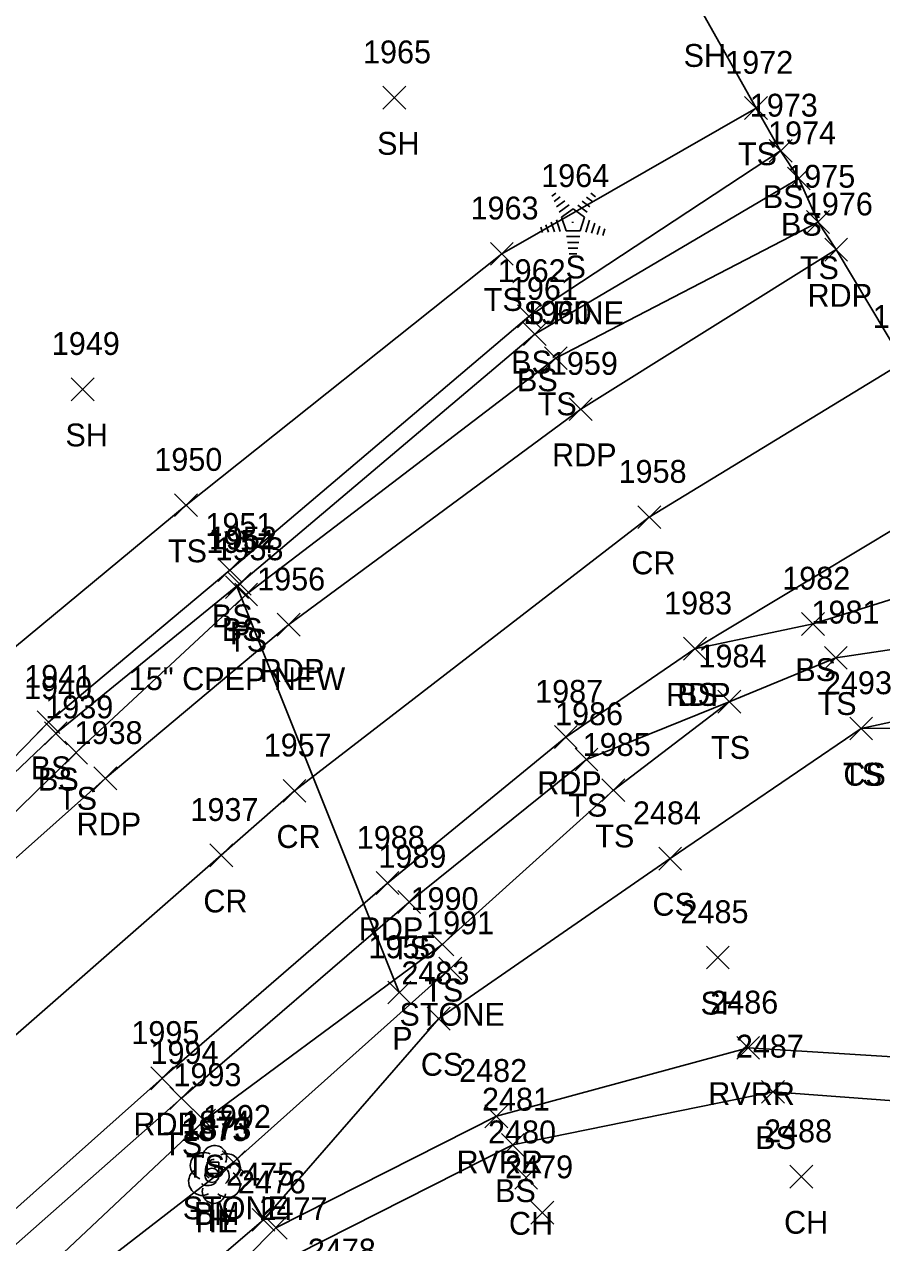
# Model space of a CAD drawing. Extents: x 1459992 to 1461532, y 647785 to 648535.
# Drawn here: x 1461347.9 to 1461422.9, y 648356.5 to 648463.1 of the extents above; entities that cross this region are included whole.
import ezdxf

# ---------------------------------------------------------------- set-up
doc = ezdxf.new("R2010")
doc.units = 0
for name, color, linetype in [('C_A', 7, 'Continuous'), ('C_I', 7, 'Continuous'), ('CBP', 7, 'Continuous'), ('CPBM', 7, 'Continuous'), ('D_A', 7, 'Continuous'), ('D_C', 7, 'Continuous'), ('D_I', 7, 'Continuous'), ('D_TIC', 7, 'Continuous'), ('DCP', 7, 'Continuous'), ('L_A', 7, 'Continuous'), ('L_C', 7, 'Continuous'), ('L_I', 7, 'Continuous'), ('L_TIC', 7, 'Continuous'), ('LASF', 7, 'Continuous'), ('LAWE', 7, 'Continuous'), ('LELB', 7, 'Continuous'), ('LSOGP', 7, 'Continuous'), ('LTC', 7, 'Continuous'), ('LTD', 7, 'Continuous'), ('P_A', 7, 'Continuous'), ('P_I', 7, 'Continuous'), ('P_TIC', 7, 'Continuous'), ('PET', 7, 'Continuous'), ('PRC', 7, 'Continuous')]:
    doc.layers.add(name, color=color, linetype=linetype)

msp = doc.modelspace()

# ---------------------------------------------------------------- linework, layer by layer
at = {"layer": 'CBP'}
for radius in [0.625, 0.0833]:
    msp.add_circle((1461364.35, 648362.4), radius, dxfattribs=at)
at = {"layer": 'CPBM'}
for p, q in [((1461363.94, 648362.56), (1461363.94, 648363.56)), ((1461363.94, 648363.56), (1461364.94, 648363.56)), ((1461364.94, 648363.56), (1461364.94, 648362.56)), ((1461364.94, 648362.56), (1461363.94, 648362.56)), ((1461364.44, 648363.06), (1461364.44, 648363.06)), ((1461364.44, 648363.06), (1461364.44, 648363.06))]:
    msp.add_line(p, q, dxfattribs=at)
at = {"layer": 'D_TIC'}
for points in [[(1461365.55, 648412.85), (1461367.55, 648414.85)], [(1461367.55, 648412.85), (1461365.55, 648414.85)], [(1461379.74, 648377.39), (1461381.74, 648379.39)], [(1461381.74, 648377.39), (1461379.74, 648379.39)]]:
    msp.add_lwpolyline(points, dxfattribs=at)
at = {"layer": 'DCP'}
msp.add_lwpolyline([(1461366.55, 648413.85), (1461380.74, 648378.39)], dxfattribs=at)
at = {"layer": 'L_TIC'}
for points in [[(1461379.31, 648455.68), (1461381.31, 648457.68)], [(1461381.31, 648455.68), (1461379.31, 648457.68)], [(1461410.96, 648454.77), (1461412.96, 648456.77)], [(1461412.96, 648454.77), (1461410.96, 648456.77)], [(1461413.11, 648451.02), (1461415.11, 648453.02)], [(1461415.11, 648451.02), (1461413.11, 648453.02)], [(1461414.7, 648448.6), (1461416.7, 648450.6)], [(1461416.7, 648448.6), (1461414.7, 648450.6)], [(1461416.38, 648444.8), (1461418.38, 648446.8)], [(1461418.38, 648444.8), (1461416.38, 648446.8)], [(1461388.72, 648442.02), (1461390.72, 648444.02)], [(1461390.72, 648442.02), (1461388.72, 648444.02)], [(1461391.09, 648436.54), (1461393.09, 648438.54)], [(1461393.09, 648436.54), (1461391.09, 648438.54)], [(1461391.6, 648434.99), (1461393.6, 648436.99)], [(1461393.6, 648434.99), (1461391.6, 648436.99)], [(1461393.44, 648432.89), (1461395.44, 648434.89)], [(1461395.44, 648432.89), (1461393.44, 648434.89)], [(1461352.04, 648430.17), (1461354.04, 648432.17)], [(1461354.04, 648430.17), (1461352.04, 648432.17)], [(1461361.09, 648420.03), (1461363.09, 648422.03)], [(1461363.09, 648420.03), (1461361.09, 648422.03)], [(1461364.91, 648414.34), (1461366.91, 648416.34)], [(1461366.91, 648414.34), (1461364.91, 648416.34)], [(1461365.77, 648413.15), (1461367.77, 648415.15)], [(1461367.77, 648413.15), (1461365.77, 648415.15)], [(1461366.35, 648412.21), (1461368.35, 648414.21)], [(1461368.35, 648412.21), (1461366.35, 648414.21)], [(1461415.95, 648409.64), (1461417.95, 648411.64)], [(1461417.95, 648409.64), (1461415.95, 648411.64)], [(1461405.61, 648407.47), (1461407.61, 648409.47)], [(1461407.61, 648407.47), (1461405.61, 648409.47)], [(1461417.94, 648406.67), (1461419.94, 648408.67)], [(1461419.94, 648406.67), (1461417.94, 648408.67)], [(1461408.62, 648402.83), (1461410.62, 648404.83)], [(1461410.62, 648402.83), (1461408.62, 648404.83)], [(1461408.62, 648402.83), (1461410.62, 648404.83)], [(1461410.62, 648402.83), (1461408.62, 648404.83)], [(1461349.05, 648401.05), (1461351.05, 648403.05)], [(1461351.05, 648401.05), (1461349.05, 648403.05)], [(1461349.69, 648400.06), (1461351.69, 648402.06)], [(1461351.69, 648400.06), (1461349.69, 648402.06)], [(1461420.16, 648400.49), (1461422.16, 648402.49)], [(1461422.16, 648400.49), (1461420.16, 648402.49)], [(1461420.16, 648400.49), (1461422.16, 648402.49)], [(1461422.16, 648400.49), (1461420.16, 648402.49)], [(1461351.47, 648398.38), (1461353.47, 648400.38)], [(1461353.47, 648398.38), (1461351.47, 648400.38)], [(1461396.12, 648397.78), (1461398.12, 648399.78)], [(1461398.12, 648397.78), (1461396.12, 648399.78)], [(1461398.48, 648395.09), (1461400.48, 648397.09)], [(1461400.48, 648395.09), (1461398.48, 648397.09)], [(1461403.45, 648389.11), (1461405.45, 648391.11)], [(1461405.45, 648389.11), (1461403.45, 648391.11)], [(1461380.61, 648385.31), (1461382.61, 648387.31)], [(1461382.61, 648385.31), (1461380.61, 648387.31)], [(1461383.51, 648381.6), (1461385.51, 648383.6)], [(1461385.51, 648381.6), (1461383.51, 648383.6)], [(1461384.21, 648379.49), (1461386.21, 648381.49)], [(1461386.21, 648379.49), (1461384.21, 648381.49)], [(1461407.61, 648380.46), (1461409.61, 648382.46)], [(1461409.61, 648380.46), (1461407.61, 648382.46)], [(1461383.19, 648375.11), (1461385.19, 648377.11)], [(1461385.19, 648375.11), (1461383.19, 648377.11)], [(1461410.27, 648372.55), (1461412.27, 648374.55)], [(1461412.27, 648372.55), (1461410.27, 648374.55)], [(1461360.68, 648368.15), (1461362.68, 648370.15)], [(1461362.68, 648368.15), (1461360.68, 648370.15)], [(1461412.45, 648368.7), (1461414.45, 648370.7)], [(1461414.45, 648368.7), (1461412.45, 648370.7)], [(1461362.67, 648366.2), (1461364.67, 648368.2)], [(1461364.67, 648366.2), (1461362.67, 648368.2)], [(1461388.24, 648366.57), (1461390.24, 648368.57)], [(1461390.24, 648366.57), (1461388.24, 648368.57)], [(1461389.68, 648364.06), (1461391.68, 648366.06)], [(1461391.68, 648364.06), (1461389.68, 648366.06)], [(1461365.25, 648362.55), (1461367.25, 648364.55)], [(1461367.25, 648362.55), (1461365.25, 648364.55)], [(1461390.85, 648361.2), (1461392.85, 648363.2)], [(1461392.85, 648361.2), (1461390.85, 648363.2)], [(1461414.92, 648361.29), (1461416.92, 648363.29)], [(1461416.92, 648361.29), (1461414.92, 648363.29)], [(1461392.26, 648358.14), (1461394.26, 648360.14)], [(1461394.26, 648358.14), (1461392.26, 648360.14)], [(1461367.86, 648357.51), (1461369.86, 648359.51)], [(1461369.86, 648357.51), (1461367.86, 648359.51)], [(1461368.94, 648356.82), (1461370.94, 648358.82)], [(1461370.94, 648356.82), (1461368.94, 648358.82)]]:
    msp.add_lwpolyline(points, dxfattribs=at)
at = {"layer": 'LASF'}
msp.add_lwpolyline([(1461385.21, 648380.49), (1461366.25, 648363.55), (1461348.1, 648349.52), (1461330.91, 648328.28), (1461323.07, 648320.21), (1461313.49, 648297.12), (1461306.87, 648275.61), (1461301.29, 648261.14), (1461300.89, 648254.87), (1461298.6, 648250.96), (1461295.29, 648245.18), (1461300.61, 648235.35), (1461302.66, 648226.75), (1461299.86, 648225.18), (1461298.5, 648223.6), (1461297.24, 648222.36)], dxfattribs=at)
at = {"layer": 'LAWE'}
msp.add_lwpolyline([(1461302.49, 648251.41), (1461304.73, 648255.86), (1461311.51, 648272.05), (1461318.18, 648292.35), (1461320.88, 648299.25), (1461325.88, 648305.32), (1461332.95, 648314.57), (1461346.56, 648331.41), (1461356.78, 648344.51), (1461369.94, 648357.82), (1461389.24, 648367.57), (1461411.27, 648373.55), (1461437.48, 648371.92), (1461454.45, 648377.93), (1461478.94, 648382.17)], dxfattribs=at)
at = {"layer": 'LELB'}
for points in [[(1461053.3, 648342.88), (1461057.1, 648347.56), (1461103.6, 648329.25), (1461132.09, 648319.28), (1461156.26, 648311.83), (1461179.8, 648313.29), (1461203.15, 648318.77), (1461223.06, 648334.41), (1461252.96, 648329.42), (1461275.76, 648346.01), (1461293.92, 648360.57), (1461297.9, 648376.52), (1461309.92, 648382.32), (1461323.28, 648384.14), (1461344.65, 648406.6), (1461362.09, 648421.03), (1461389.72, 648443.02), (1461411.96, 648455.77)], [(1461328.64, 648380.09), (1461350.05, 648402.05), (1461365.91, 648415.34), (1461392.09, 648437.54), (1461414.11, 648452.02)], [(1461045.75, 648345.16), (1461053.3, 648342.88), (1461099.57, 648323.3), (1461128.93, 648312.14), (1461154.02, 648304.18), (1461179.99, 648301.37), (1461204.48, 648303), (1461231.37, 648312.49), (1461255.41, 648321.87), (1461278.91, 648340.15), (1461298.64, 648355.28), (1461307.84, 648362.71), (1461328.64, 648380.09), (1461350.69, 648401.06), (1461366.77, 648414.15), (1461392.6, 648435.99), (1461415.7, 648449.6)], [(1460952.34, 648377.13), (1460985.69, 648362.66), (1461027.43, 648346.63), (1461054.39, 648335.28), (1461097.58, 648319.81), (1461127.3, 648308.18), (1461153.51, 648301.33), (1461179.78, 648297.83), (1461204.84, 648300.47), (1461233.15, 648308.09), (1461257.01, 648318.59), (1461281.51, 648336.52), (1461300.79, 648352.57), (1461310.07, 648360.68), (1461331.77, 648379.2), (1461352.47, 648399.38), (1461367.35, 648413.21), (1461394.44, 648433.89), (1461417.38, 648445.8)], [(1461435.34, 648416.39), (1461416.95, 648410.64), (1461406.61, 648408.47)], [(1461437.89, 648410.49), (1461418.94, 648407.67), (1461409.62, 648403.83), (1461397.12, 648398.78), (1461381.61, 648386.31), (1461361.68, 648369.15), (1461343.97, 648353.54), (1461325.1, 648333.83), (1461318.7, 648322.25), (1461308.65, 648307.17), (1461301.59, 648300.07), (1461298.1, 648291.15), (1461293.27, 648263.28), (1461293.55, 648252.72), (1461292.9, 648243.51), (1461295.99, 648233.83), (1461296.73, 648225.48), (1461296.73, 648222.49)], [(1461327.54, 648316.41), (1461343.1, 648334.57), (1461354.42, 648346.15), (1461368.86, 648358.51), (1461384.19, 648376.11), (1461404.45, 648390.11), (1461421.16, 648401.49), (1461440.47, 648405.65), (1461476.93, 648404.7)], [(1461409.62, 648403.83), (1461399.48, 648396.09), (1461384.51, 648382.6), (1461363.67, 648367.2), (1461346.46, 648351.01), (1461329.68, 648330.05), (1461321.26, 648319.56), (1461311.8, 648297.78), (1461304.88, 648276.19), (1461298.28, 648261.22), (1461298.6, 648250.96)], [(1461421.16, 648401.49), (1461442.53, 648401.65), (1461477.3, 648395.7)], [(1461308.56, 648239.32), (1461311.25, 648242.53), (1461308.11, 648247.08), (1461308.77, 648252.86), (1461315.17, 648270.04), (1461321.58, 648291.02), (1461329.02, 648302.01), (1461334.85, 648312.35), (1461349.26, 648326.91), (1461358.54, 648342.56), (1461371.77, 648355.49), (1461390.68, 648365.06), (1461413.45, 648369.7), (1461437.72, 648367.9), (1461455.54, 648374.9), (1461479.25, 648378.91)]]:
    msp.add_lwpolyline(points, dxfattribs=at)
at = {"layer": 'LSOGP'}
msp.add_lwpolyline([(1461424.86, 648433.53), (1461418.97, 648443.38), (1461417.38, 648445.8), (1461415.7, 648449.6), (1461414.11, 648452.02), (1461411.96, 648455.77), (1461407.13, 648464.37), (1461399.06, 648478.69), (1461388.86, 648495.69), (1461378.34, 648513.06), (1461354.54, 648501.82), (1461314.28, 648477.24), (1461287.25, 648458.7)], dxfattribs=at)
at = {"layer": 'LTC'}
for p, q in [((1461394.09, 648448.07), (1461394.45, 648448.32)), ((1461394.3, 648447.6), (1461394.83, 648447.99)), ((1461394.51, 648447.14), (1461395.22, 648447.65)), ((1461396.75, 648447.61), (1461397.43, 648447.12)), ((1461397.12, 648447.96), (1461397.67, 648447.56)), ((1461397.49, 648448.31), (1461397.91, 648448)), ((1461394.72, 648446.67), (1461395.6, 648447.31)), ((1461394.95, 648446.22), (1461395.96, 648446.95)), ((1461395.96, 648446.95), (1461396.96, 648446.22)), ((1461396.38, 648447.26), (1461397.19, 648446.67)), ((1461393.58, 648445.56), (1461393.79, 648444.91)), ((1461394.04, 648445.78), (1461394.31, 648444.94)), ((1461394.49, 648446), (1461394.82, 648444.98)), ((1461394.95, 648446.22), (1461395.34, 648445.02)), ((1461396.96, 648446.22), (1461396.57, 648445.02)), ((1461397.39, 648445.95), (1461397.06, 648444.91)), ((1461397.84, 648445.7), (1461397.55, 648444.82)), ((1461398.28, 648445.45), (1461398.05, 648444.72)), ((1461393.13, 648445.35), (1461393.28, 648444.88)), ((1461396.57, 648445.02), (1461395.34, 648445.02)), ((1461396.53, 648444.52), (1461395.38, 648444.52)), ((1461398.73, 648445.2), (1461398.54, 648444.63)), ((1461396.44, 648444.02), (1461395.46, 648444.02)), ((1461396.36, 648443.52), (1461395.53, 648443.52)), ((1461396.28, 648443.02), (1461395.6, 648443.02))]:
    msp.add_line(p, q, dxfattribs=at)
at = {"layer": 'LTD'}
msp.add_line((1461364.54, 648362.53), (1461364.54, 648362.53), dxfattribs=at)
msp.add_line((1461364.54, 648362.53), (1461364.54, 648362.53), dxfattribs=at)
msp.add_arc((1461364.59, 648363.96), 1.05, 335.5272, 180.9563, dxfattribs=at)
for centre, major_axis, ratio, start_param, end_param in [((1461363.75, 648363.19), (1.21, -0.51), 0.895232, 1.570796, 4.712389), ((1461365.58, 648363.11), (-1.14, -0.48), 0.949671, 1.570796, 4.712389), ((1461364.33, 648362.98), (-0.208, -0.792), 0.645439, 3.141593, 6.283185), ((1461363.46, 648361.82), (0.58, -1.04), 0.959034, 3.141593, 6.283185), ((1461365.04, 648362.36), (-0.5, 0.667), 0.989748, 3.141593, 6.283185), ((1461365.54, 648361.69), (-1.09, 0.79), 0.841452, 1.570796, 4.712389), ((1461364.54, 648361.03), (0.26, 1.06), 0.942809, 1.570796, 4.712389), ((1461364.08, 648361.78), (-0.625, -0.083), 0.423636, 0, 3.141593)]:
    msp.add_ellipse(centre, major_axis=major_axis, ratio=ratio, start_param=start_param, end_param=end_param, dxfattribs=at)
at = {"layer": 'P_TIC'}
for points in [[(1461417.97, 648442.38), (1461419.97, 648444.38)], [(1461419.97, 648442.38), (1461417.97, 648444.38)], [(1461395.62, 648428.43), (1461397.62, 648430.43)], [(1461397.62, 648428.43), (1461395.62, 648430.43)], [(1461401.62, 648418.98), (1461403.62, 648420.98)], [(1461403.62, 648418.98), (1461401.62, 648420.98)], [(1461370.06, 648409.57), (1461372.06, 648411.57)], [(1461372.06, 648409.57), (1461370.06, 648411.57)], [(1461405.61, 648407.47), (1461407.61, 648409.47)], [(1461407.61, 648407.47), (1461405.61, 648409.47)], [(1461394.32, 648399.74), (1461396.32, 648401.74)], [(1461396.32, 648399.74), (1461394.32, 648401.74)], [(1461354.02, 648396.13), (1461356.02, 648398.13)], [(1461356.02, 648396.13), (1461354.02, 648398.13)], [(1461370.57, 648395.04), (1461372.57, 648397.04)], [(1461372.57, 648395.04), (1461370.57, 648397.04)], [(1461364.17, 648389.4), (1461366.17, 648391.4)], [(1461366.17, 648389.4), (1461364.17, 648391.4)], [(1461378.71, 648386.97), (1461380.71, 648388.97)], [(1461380.71, 648386.97), (1461378.71, 648388.97)], [(1461359, 648369.89), (1461361, 648371.89)], [(1461361, 648369.89), (1461359, 648371.89)]]:
    msp.add_lwpolyline(points, dxfattribs=at)
at = {"layer": 'PET'}
for points in [[(1460950.93, 648374.58), (1460984.69, 648360.32), (1461025.42, 648343.73), (1461053.38, 648332.51), (1461095.05, 648316.17), (1461126.17, 648304.95), (1461152.62, 648298.48), (1461179.86, 648295.54), (1461205.35, 648297.28), (1461234.43, 648304.94), (1461258.07, 648315.7), (1461283.68, 648333.5), (1461302.87, 648349.75), (1461333.02, 648377.55), (1461355.02, 648397.13), (1461371.06, 648410.57), (1461396.62, 648429.43), (1461418.97, 648443.38)], [(1461431.71, 648423.56), (1461406.61, 648408.47), (1461395.32, 648400.74), (1461379.71, 648387.97), (1461360, 648370.89), (1461342.5, 648355.32), (1461322.76, 648336.16), (1461306.54, 648318.18), (1461292.23, 648305.65), (1461275.7, 648293.86), (1461255.23, 648282.83), (1461238.6, 648275.7), (1461226.2, 648272.49), (1461213.09, 648269.85), (1461197.04, 648267.63), (1461176.94, 648267.36), (1461164.21, 648269.58)]]:
    msp.add_lwpolyline(points, dxfattribs=at)
at = {"layer": 'PRC'}
msp.add_lwpolyline([(1460946.83, 648364.55), (1460979.81, 648350.87), (1461020.89, 648333.41), (1461048.05, 648322.3), (1461089.53, 648305.67), (1461120.42, 648294.12), (1461149.17, 648286), (1461180.56, 648282.29), (1461207.18, 648283.7), (1461238.84, 648291.79), (1461263.78, 648303.51), (1461290.77, 648322.92), (1461310.31, 648340.94), (1461342.22, 648370.37), (1461365.17, 648390.4), (1461371.57, 648396.04), (1461402.62, 648419.98), (1461424.86, 648433.53)], dxfattribs=at)

# ---------------------------------------------------------------- texts
at = {"layer": 'C_A'}
for s, p in [('TIE', (1461362.43, 648357.4)), ('BM', (1461362.76, 648358.06))]:
    msp.add_text(s, height=2, dxfattribs=at).set_placement(p)
at = {"layer": 'C_I'}
for s, p in [('1874', (1461361.75, 648366.06)), ('1875', (1461361.65, 648365.4))]:
    msp.add_text(s, height=2, dxfattribs=at).set_placement(p)
at = {"layer": 'D_A'}
for p in [(1461365.93, 648408.85), (1461380.12, 648373.39)]:
    msp.add_text('P', height=2, dxfattribs=at).set_placement(p)
at = {"layer": 'D_C'}
msp.add_text('15" CPEP NEW', height=2, dxfattribs=at).set_placement((1461357.08, 648404.85))
at = {"layer": 'D_I'}
for s, p in [('1954', (1461363.86, 648416.85)), ('1955', (1461378.05, 648381.39))]:
    msp.add_text(s, height=2, dxfattribs=at).set_placement(p)
at = {"layer": 'L_A'}
for s, p in [('SH', (1461405.62, 648459.37)), ('SH', (1461378.8, 648451.68)), ('TS', (1461410.37, 648450.77)), ('BS', (1461412.55, 648447.02)), ('BS', (1461414.14, 648444.6)), ('S', (1461395.29, 648440.86)), ('TS', (1461415.79, 648440.8)), ('TS', (1461388.13, 648438.02)), ('BS', (1461390.53, 648432.54)), ('BS', (1461391.04, 648430.99)), ('TS', (1461392.85, 648428.89)), ('SH', (1461351.53, 648426.17)), ('TS', (1461360.5, 648416.03)), ('BS', (1461364.35, 648410.34)), ('BS', (1461365.21, 648409.15)), ('TS', (1461365.76, 648408.21)), ('BS', (1461415.39, 648405.64)), ('BS', (1461405.05, 648403.47)), ('TS', (1461417.34, 648402.67)), ('TS', (1461408.02, 648398.83)), ('TS', (1461408.02, 648398.83)), ('BS', (1461348.49, 648397.05)), ('TS', (1461419.57, 648396.49)), ('CS', (1461419.6, 648396.49)), ('BS', (1461349.13, 648396.06)), ('TS', (1461350.88, 648394.38)), ('TS', (1461395.53, 648393.78)), ('TS', (1461397.89, 648391.09)), ('CS', (1461402.89, 648385.11)), ('TS', (1461380.02, 648381.31)), ('TS', (1461382.92, 648377.6)), ('SH', (1461407.1, 648376.46)), ('STONE', (1461380.76, 648375.49)), ('CS', (1461382.63, 648371.11)), ('RVRR', (1461407.78, 648368.55)), ('BS', (1461411.89, 648364.7)), ('TS', (1461360.08, 648364.15)), ('RVRR', (1461385.75, 648362.57)), ('TS', (1461362.08, 648362.2)), ('BS', (1461389.12, 648360.06)), ('STONE', (1461361.79, 648358.55)), ('H', (1461363.97, 648357.53)), ('CH', (1461390.34, 648357.2)), ('CH', (1461414.41, 648357.29))]:
    msp.add_text(s, height=2, dxfattribs=at).set_placement(p)
at = {"layer": 'L_C'}
msp.add_text('S.PINE', height=2, dxfattribs=at).set_placement((1461391.63, 648436.86))
at = {"layer": 'L_I'}
for s, p in [('1965', (1461377.57, 648459.68)), ('1972', (1461409.26, 648458.77)), ('1973', (1461411.41, 648455.02)), ('1974', (1461413.01, 648452.6)), ('1964', (1461393.16, 648448.86)), ('1975', (1461414.69, 648448.8)), ('1963', (1461386.98, 648446.02)), ('1962', (1461389.35, 648440.54)), ('1961', (1461390.42, 648438.99)), ('1960', (1461391.61, 648436.89)), ('1949', (1461350.34, 648434.17)), ('1950', (1461359.31, 648424.03)), ('1951', (1461363.78, 648418.34)), ('1952', (1461364.08, 648417.15)), ('1953', (1461364.66, 648416.21)), ('1982', (1461414.25, 648413.64)), ('1983', (1461403.91, 648411.47)), ('1981', (1461416.81, 648410.67)), ('1984', (1461406.92, 648406.83)), ('1984', (1461406.92, 648406.83)), ('1941', (1461347.93, 648405.05)), ('1940', (1461347.91, 648404.06)), ('2493', (1461417.9, 648404.49)), ('2493', (1461417.9, 648404.49)), ('1939', (1461349.77, 648402.38)), ('1986', (1461394.37, 648401.78)), ('1985', (1461396.79, 648399.09)), ('2484', (1461401.19, 648393.11)), ('1989', (1461378.91, 648389.31)), ('1990', (1461381.73, 648385.6)), ('2485', (1461405.35, 648384.46)), ('1991', (1461383.09, 648383.49)), ('2483', (1461380.93, 648379.11)), ('2486', (1461407.95, 648376.55)), ('1994', (1461358.98, 648372.15)), ('2487', (1461410.19, 648372.7)), ('1993', (1461360.98, 648370.2)), ('2482', (1461385.98, 648370.57)), ('2481', (1461387.98, 648368.06)), ('1992', (1461363.56, 648366.55)), ('1873', (1461361.85, 648365.53)), ('2480', (1461388.51, 648365.2)), ('2488', (1461412.66, 648365.29)), ('2475', (1461365.6, 648361.51)), ('2479', (1461390, 648362.14)), ('2476', (1461366.62, 648360.82)), ('2477', (1461368.51, 648358.49)), ('2478', (1461372.74, 648354.86))]:
    msp.add_text(s, height=2, dxfattribs=at).set_placement(p)
at = {"layer": 'LTC'}
msp.add_text('.', height=1.04, rotation=270, dxfattribs=at).set_placement((1461395.84, 648445.96))
at = {"layer": 'P_A'}
for s, p in [('RDP', (1461416.46, 648438.38)), ('RDP', (1461394.11, 648424.43)), ('CR', (1461401.05, 648414.98)), ('RDP', (1461368.55, 648405.57)), ('RDP', (1461404.09, 648403.47)), ('RDP', (1461392.81, 648395.74)), ('RDP', (1461352.51, 648392.13)), ('CR', (1461370, 648391.04)), ('CR', (1461363.6, 648385.4)), ('RDP', (1461377.2, 648382.97)), ('RDP', (1461357.48, 648365.89))]:
    msp.add_text(s, height=2, dxfattribs=at).set_placement(p)
at = {"layer": 'P_I'}
for s, p in [('1976', (1461416.23, 648446.38)), ('1977', (1461422.17, 648436.53)), ('1959', (1461393.92, 648432.43)), ('1958', (1461399.93, 648422.98)), ('1956', (1461368.31, 648413.57)), ('1983', (1461403.91, 648411.47)), ('1987', (1461392.63, 648403.74)), ('1938', (1461352.33, 648400.13)), ('1957', (1461368.88, 648399.04)), ('1937', (1461362.47, 648393.4)), ('1988', (1461377.02, 648390.97)), ('1995', (1461357.3, 648373.89))]:
    msp.add_text(s, height=2, dxfattribs=at).set_placement(p)

doc.saveas('drawing.dxf')
